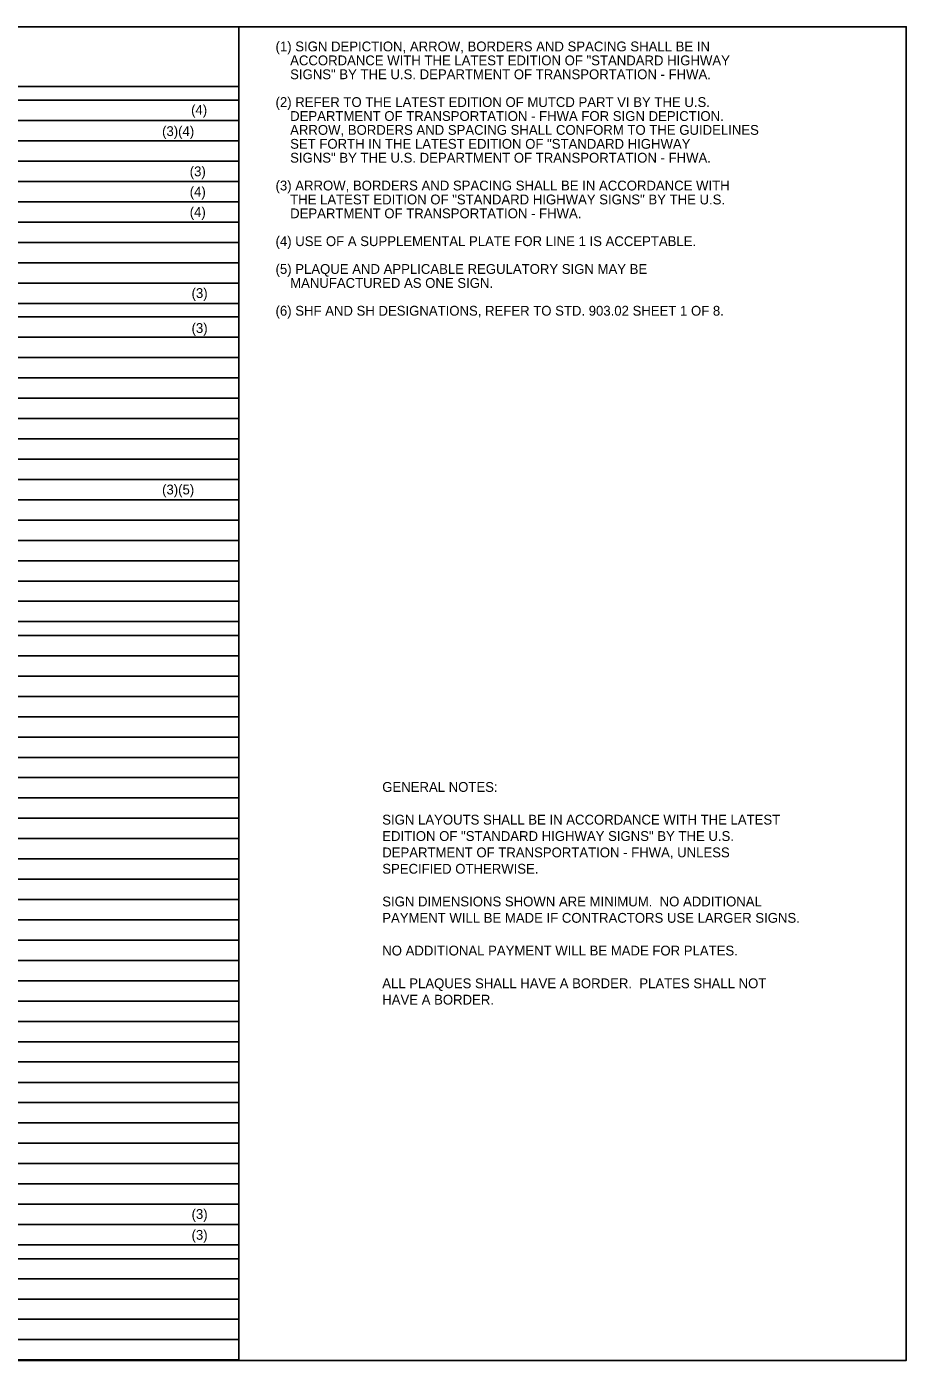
# Model space of a CAD drawing. Extents: x -439.1 to -407.9, y -458.1 to -437.7.
# Drawn here: x -421.29 to -407.86, y -458.05 to -437.68 of the extents above; entities that cross this region are included whole.
import ezdxf

# ---------------------------------------------------------------- set-up
doc = ezdxf.new("R2010")
doc.units = 0
for name, color, linetype in [('Common-Notes', 7, 'Continuous'), ('Draft_Named_Boundary', 7, 'Continuous'), ('Level 4', 7, 'Continuous'), ('Level 45', 7, 'Continuous')]:
    doc.layers.add(name, color=color, linetype=linetype)

msp = doc.modelspace()

# ---------------------------------------------------------------- linework, layer by layer
at = {"layer": 'Common-Notes'}
msp.add_line((-439.109, -445.834), (-418.049, -445.834), dxfattribs=at)
at = {"layer": 'Draft_Named_Boundary'}
msp.add_lwpolyline([(-439.109, -458.051), (-407.859, -458.051), (-407.859, -437.676), (-439.109, -437.676)], close=True, dxfattribs=at)
at = {"layer": 'Level 4'}
for p, q in [((-439.109, -437.676), (-418.049, -437.676)), ((-418.049, -437.676), (-418.049, -458.044)), ((-439.109, -438.59), (-418.049, -438.59)), ((-439.109, -438.8), (-418.049, -438.8)), ((-439.109, -439.11), (-418.049, -439.11)), ((-439.109, -439.421), (-418.049, -439.421)), ((-439.109, -439.731), (-418.049, -439.731)), ((-439.109, -440.041), (-418.049, -440.041)), ((-439.109, -440.351), (-418.049, -440.351)), ((-439.109, -440.662), (-418.049, -440.662)), ((-439.109, -440.972), (-418.049, -440.972)), ((-439.109, -441.282), (-418.049, -441.282)), ((-439.109, -441.593), (-418.049, -441.593)), ((-439.109, -441.903), (-418.049, -441.903)), ((-439.109, -442.11), (-418.049, -442.11)), ((-439.109, -442.421), (-418.049, -442.421)), ((-439.109, -442.731), (-418.049, -442.731)), ((-439.109, -443.041), (-418.049, -443.041)), ((-439.109, -443.352), (-418.049, -443.352)), ((-439.109, -443.662), (-418.049, -443.662)), ((-439.109, -443.972), (-418.049, -443.972)), ((-439.109, -444.283), (-418.049, -444.283)), ((-439.109, -444.593), (-418.049, -444.593)), ((-439.109, -444.903), (-418.049, -444.903)), ((-418.762, -444.903), (-418.763, -444.903)), ((-439.109, -445.214), (-418.049, -445.214)), ((-439.109, -445.524), (-418.049, -445.524)), ((-439.109, -446.145), (-418.049, -446.145)), ((-439.109, -446.455), (-418.049, -446.455)), ((-418.049, -446.765), (-439.109, -446.765)), ((-418.049, -446.977), (-439.109, -446.977)), ((-439.109, -447.287), (-418.049, -447.287)), ((-439.109, -447.597), (-418.049, -447.597)), ((-439.109, -447.908), (-418.049, -447.908)), ((-439.109, -448.218), (-418.049, -448.218)), ((-439.109, -448.528), (-418.049, -448.528)), ((-439.109, -448.839), (-418.049, -448.839)), ((-439.109, -449.149), (-418.049, -449.149)), ((-439.109, -449.459), (-418.049, -449.459)), ((-439.109, -449.77), (-418.049, -449.77)), ((-439.109, -450.08), (-418.049, -450.08)), ((-439.109, -450.39), (-418.049, -450.39)), ((-439.109, -450.701), (-418.049, -450.701)), ((-439.109, -451.011), (-418.049, -451.011)), ((-439.109, -451.321), (-418.049, -451.321)), ((-439.109, -451.632), (-418.049, -451.632)), ((-439.109, -451.942), (-418.049, -451.942)), ((-439.109, -452.252), (-418.049, -452.252)), ((-439.109, -452.563), (-418.049, -452.563)), ((-439.109, -452.873), (-418.049, -452.873)), ((-439.109, -453.183), (-418.049, -453.183)), ((-439.109, -453.493), (-418.049, -453.493)), ((-439.109, -453.804), (-418.049, -453.804)), ((-439.109, -454.114), (-418.049, -454.114)), ((-439.109, -454.424), (-418.049, -454.424)), ((-439.109, -454.735), (-418.049, -454.735)), ((-439.109, -455.045), (-418.049, -455.045)), ((-439.109, -455.355), (-418.049, -455.355)), ((-439.109, -455.666), (-418.049, -455.666)), ((-439.109, -455.976), (-418.049, -455.976)), ((-439.109, -456.286), (-418.049, -456.286)), ((-439.109, -456.498), (-418.049, -456.498)), ((-439.109, -456.808), (-418.049, -456.808)), ((-439.109, -457.118), (-418.049, -457.118)), ((-439.109, -457.424), (-418.049, -457.424)), ((-439.109, -457.735), (-418.049, -457.735)), ((-439.109, -458.044), (-418.049, -458.044))]:
    msp.add_line(p, q, dxfattribs=at)

# ---------------------------------------------------------------- texts
for s, p in [('(1) SIGN DEPICTION, ARROW, BORDERS AND SPACING SHALL BE IN ', (-417.488, -438.053)), ('    ACCORDANCE WITH THE LATEST EDITION OF "STANDARD HIGHWAY ', (-417.488, -438.266)), ('    SIGNS" BY THE U.S. DEPARTMENT OF TRANSPORTATION - FHWA.', (-417.488, -438.478)), ('(4)', (-418.777, -439.021)), ('(2) REFER TO THE LATEST EDITION OF MUTCD PART VI BY THE U.S. ', (-417.488, -438.903)), ('    DEPARTMENT OF TRANSPORTATION - FHWA FOR SIGN DEPICTION. ', (-417.488, -439.116)), ('(3)(4)', (-419.22, -439.347)), ('    ARROW, BORDERS AND SPACING SHALL CONFORM TO THE GUIDELINES ', (-417.488, -439.328)), ('    SET FORTH IN THE LATEST EDITION OF "STANDARD HIGHWAY ', (-417.488, -439.541)), ('    SIGNS" BY THE U.S. DEPARTMENT OF TRANSPORTATION - FHWA.', (-417.488, -439.753)), ('(3)', (-418.798, -439.961)), ('(3) ARROW, BORDERS AND SPACING SHALL BE IN ACCORDANCE WITH ', (-417.488, -440.178)), ('(4)', (-418.798, -440.272)), ('    THE LATEST EDITION OF "STANDARD HIGHWAY SIGNS" BY THE U.S. ', (-417.488, -440.391)), ('(4)', (-418.798, -440.582)), ('    DEPARTMENT OF TRANSPORTATION - FHWA.', (-417.488, -440.603)), ('(4) USE OF A SUPPLEMENTAL PLATE FOR LINE 1 IS ACCEPTABLE.', (-417.488, -441.028)), ('(5) PLAQUE AND APPLICABLE REGULATORY SIGN MAY BE ', (-417.488, -441.453)), ('    MANUFACTURED AS ONE SIGN.', (-417.488, -441.666)), ('(3)', (-418.77, -441.821)), ('(6) SHF AND SH DESIGNATIONS, REFER TO STD. 903.02 SHEET 1 OF 8.', (-417.488, -442.091)), ('(3)', (-418.77, -442.355)), ('(3)(5)', (-419.22, -444.822)), ('(3)', (-418.77, -455.891)), ('(3)', (-418.77, -456.209))]:
    msp.add_text(s, height=0.15, dxfattribs=at).set_placement(p)
at = {"layer": 'Level 45'}
for s, p in [('GENERAL NOTES:', (-415.859, -449.366)), ('SIGN LAYOUTS SHALL BE IN ACCORDANCE WITH THE LATEST ', (-415.859, -449.866)), ('EDITION OF "STANDARD HIGHWAY SIGNS" BY THE U.S. ', (-415.859, -450.116)), ('DEPARTMENT OF TRANSPORTATION - FHWA, UNLESS ', (-415.859, -450.366)), ('SPECIFIED OTHERWISE.', (-415.859, -450.616)), ('SIGN DIMENSIONS SHOWN ARE MINIMUM.  NO ADDITIONAL ', (-415.859, -451.116)), ('PAYMENT WILL BE MADE IF CONTRACTORS USE LARGER SIGNS.', (-415.859, -451.366)), ('NO ADDITIONAL PAYMENT WILL BE MADE FOR PLATES. ', (-415.859, -451.866)), ('ALL PLAQUES SHALL HAVE A BORDER.  PLATES SHALL NOT ', (-415.859, -452.366)), ('HAVE A BORDER.', (-415.859, -452.616))]:
    msp.add_text(s, height=0.15, dxfattribs=at).set_placement(p)

doc.saveas('drawing.dxf')
